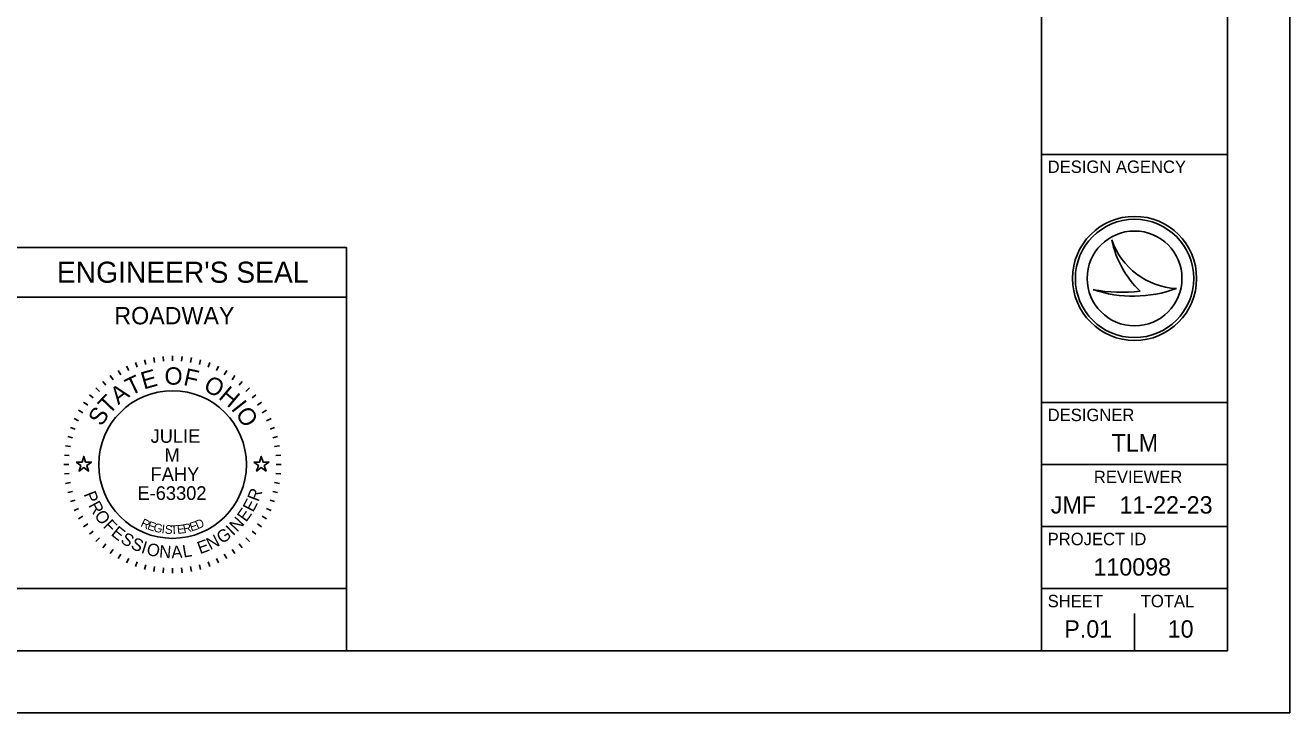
# Model space of a CAD drawing. Extents: x 0 to 34, y 0 to 22.
# Drawn here: x 23.81 to 34, y 0 to 5.54 of the extents above; entities that cross this region are included whole.
import ezdxf

# ---------------------------------------------------------------- set-up
doc = ezdxf.new("R2010")
doc.units = 0
for name, color, linetype in [('Default', 7, 'Continuous'), ('SH_Border', 7, 'Continuous'), ('SH_Cut_Line', 7, 'Continuous'), ('SH_Data', 7, 'Continuous')]:
    doc.layers.add(name, color=color, linetype=linetype)

msp = doc.modelspace()

# ---------------------------------------------------------------- linework, layer by layer
at = {"layer": 'Default'}
for points in [[(24.224, 2.02), (24.271, 2.02), (24.285, 2.065), (24.299, 2.02), (24.346, 2.02), (24.308, 1.992), (24.323, 1.948), (24.285, 1.975), (24.247, 1.948), (24.262, 1.992)], [(25.654, 2.02), (25.701, 2.02), (25.715, 2.065), (25.729, 2.02), (25.776, 2.02), (25.738, 1.992), (25.753, 1.948), (25.715, 1.975), (25.677, 1.948), (25.692, 1.992)]]:
    msp.add_lwpolyline(points, close=True, dxfattribs=at)
at = {"layer": 'SH_Border'}
for p, q in [((32, 0.5), (32, 21.5)), ((32, 4.5), (33.5, 4.5)), ((32, 2.5), (33.5, 2.5)), ((32, 2), (33.5, 2)), ((32, 1.5), (33.5, 1.5)), ((32, 1), (33.5, 1))]:
    msp.add_line(p, q, dxfattribs=at)
msp.add_lwpolyline([(1.5, 21.5), (33.5, 21.5), (33.5, 0.5), (1.5, 0.5)], close=True, dxfattribs=at)
at = {"layer": 'SH_Cut_Line'}
msp.add_lwpolyline([(0, 0), (34, 0), (34, 22), (0, 22)], close=True, dxfattribs=at)
at = {"layer": 'SH_Data'}
for p, q in [((32.567, 3.81), (32.567, 3.81)), ((23.6, 3.75), (26.4, 3.75)), ((26.4, 3.75), (26.4, 0.5)), ((32.75, 3.5), (32.75, 3.5)), ((32.417, 3.41), (32.417, 3.41)), ((33.087, 3.419), (33.087, 3.419)), ((23.6, 3.35), (26.4, 3.35)), ((24.848, 2.862), (24.855, 2.822)), ((24.924, 2.872), (24.927, 2.832)), ((25, 2.875), (25, 2.835)), ((25.076, 2.872), (25.073, 2.832)), ((25.152, 2.862), (25.145, 2.822)), ((24.563, 2.758), (24.583, 2.723)), ((24.63, 2.793), (24.647, 2.757)), ((24.701, 2.822), (24.714, 2.785)), ((24.774, 2.845), (24.784, 2.807)), ((25.226, 2.845), (25.216, 2.807)), ((25.299, 2.822), (25.286, 2.785)), ((25.37, 2.793), (25.353, 2.757)), ((25.437, 2.758), (25.417, 2.723)), ((24.438, 2.67), (24.463, 2.64)), ((24.498, 2.717), (24.521, 2.684)), ((25.502, 2.717), (25.479, 2.684)), ((25.562, 2.67), (25.537, 2.64)), ((24.33, 2.562), (24.36, 2.537)), ((24.381, 2.619), (24.41, 2.59)), ((25.619, 2.619), (25.59, 2.59)), ((25.67, 2.562), (25.64, 2.537)), ((24.283, 2.502), (24.316, 2.479)), ((25.717, 2.502), (25.684, 2.479)), ((24.207, 2.37), (24.243, 2.353)), ((24.242, 2.438), (24.277, 2.418)), ((25.758, 2.438), (25.723, 2.418)), ((25.793, 2.37), (25.757, 2.353)), ((24.178, 2.299), (24.215, 2.286)), ((25.822, 2.299), (25.785, 2.286)), ((24.138, 2.152), (24.178, 2.145)), ((24.155, 2.226), (24.193, 2.216)), ((25.845, 2.226), (25.807, 2.216)), ((25.862, 2.152), (25.822, 2.145)), ((24.128, 2.076), (24.168, 2.073)), ((25.872, 2.076), (25.832, 2.073)), ((24.125, 2), (24.165, 2)), ((25.875, 2), (25.835, 2)), ((24.128, 1.924), (24.168, 1.927)), ((24.138, 1.848), (24.178, 1.855)), ((25.862, 1.848), (25.822, 1.855)), ((25.872, 1.924), (25.832, 1.927)), ((24.155, 1.774), (24.193, 1.784)), ((25.845, 1.774), (25.807, 1.784)), ((24.178, 1.701), (24.215, 1.714)), ((24.207, 1.63), (24.243, 1.647)), ((25.793, 1.63), (25.757, 1.647)), ((25.822, 1.701), (25.785, 1.714)), ((24.242, 1.563), (24.277, 1.583)), ((25.758, 1.563), (25.723, 1.583)), ((24.283, 1.498), (24.316, 1.521)), ((24.33, 1.438), (24.36, 1.463)), ((25.67, 1.438), (25.64, 1.463)), ((25.717, 1.498), (25.684, 1.521)), ((24.381, 1.381), (24.41, 1.41)), ((24.438, 1.33), (24.463, 1.36)), ((25.562, 1.33), (25.537, 1.36)), ((25.619, 1.381), (25.59, 1.41)), ((24.498, 1.283), (24.521, 1.316)), ((24.563, 1.242), (24.583, 1.277)), ((24.63, 1.207), (24.647, 1.243)), ((25.37, 1.207), (25.353, 1.243)), ((25.437, 1.242), (25.417, 1.277)), ((25.502, 1.283), (25.479, 1.316)), ((24.701, 1.178), (24.714, 1.215)), ((24.774, 1.155), (24.784, 1.193)), ((24.848, 1.138), (24.855, 1.178)), ((24.924, 1.128), (24.927, 1.168)), ((25, 1.125), (25, 1.165)), ((25.076, 1.128), (25.073, 1.168)), ((25.152, 1.138), (25.145, 1.178)), ((25.226, 1.155), (25.216, 1.193)), ((25.299, 1.178), (25.286, 1.215)), ((32.75, 0.5), (32.75, 0.8)), ((32.375, 0.675), (32.375, 0.675)), ((23.6, 0.5), (26.4, 0.5)), ((23.6, 0.5), (26.4, 0.5))]:
    msp.add_line(p, q, dxfattribs=at)
msp.add_lwpolyline([(23.6, 0.5), (23.6, 1), (26.4, 1), (26.4, 0.5)], close=True, dxfattribs=at)
for centre, radius in [((32.75, 3.5), 0.5), ((32.75, 3.5), 0.477), ((32.75, 3.5), 0.477), ((32.75, 3.5), 0.382), ((25, 2), 0.595)]:
    msp.add_circle(centre, radius, dxfattribs=at)
for centre, radius, start, end in [((33.116, 3.998), 0.58, 198.9257, 198.9319), ((33.347, 3.97), 0.796, 191.6379, 191.6421), ((33.116, 3.998), 0.58, 198.9319, 267.1657), ((33.347, 3.97), 0.796, 191.6421, 226.0947), ((32.739, 4.37), 1.013, 251.4576, 290.0832), ((32.648, 4.654), 1.266, 259.4964, 259.4995), ((32.739, 4.37), 1.013, 251.4527, 251.4576), ((32.648, 4.654), 1.266, 259.4995, 276.6672)]:
    msp.add_arc(centre, radius, start, end, dxfattribs=at)

# ---------------------------------------------------------------- texts
for s, height, p in [('DESIGN AGENCY', 0.1, (32.05, 4.35)), ("ENGINEER'S SEAL", 0.17, (24.068, 3.465)), ('ROADWAY', 0.14, (24.531, 3.13)), ('DESIGNER', 0.1, (32.05, 2.35)), ('JULIE', 0.11, (24.823, 2.175)), ('TLM', 0.14, (32.565, 2.105)), ('M', 0.11, (24.935, 2.022)), ('FAHY', 0.11, (24.823, 1.868)), ('REVIEWER', 0.1, (32.422, 1.85)), ('E-63302', 0.11, (24.717, 1.715)), ('JMF', 0.14, (32.075, 1.605)), ('11-22-23', 0.14, (32.629, 1.605)), ('PROJECT ID', 0.1, (32.05, 1.35)), ('110098', 0.14, (32.419, 1.105)), ('SHEET', 0.1, (32.05, 0.85)), ('TOTAL', 0.1, (32.8, 0.85)), ('P.01', 0.14, (32.184, 0.605)), ('10', 0.14, (33.017, 0.605))]:
    msp.add_text(s, height=height, dxfattribs=at).set_placement(p)
for s, height, rotation, p in [('E', 0.14, 15.7571, (24.768, 2.604)), ('O', 0.14, 359.7812, (24.935, 2.644)), ('F', 0.14, 347.4362, (25.081, 2.642)), ('T', 0.14, 25.7167, (24.662, 2.552)), ('O', 0.14, 332.2586, (25.24, 2.602)), ('T', 0.14, 46.4344, (24.488, 2.396)), ('A', 0.14, 36.4747, (24.563, 2.478)), ('H', 0.14, 319.9136, (25.363, 2.536)), ('S', 0.14, 57.1924, (24.428, 2.301)), ('I', 0.14, 308.367, (25.466, 2.448)), ('O', 0.14, 303.1491, (25.502, 2.409)), ('P', 0.1, 291.494, (24.282, 1.762)), ('R', 0.1, 69.2322, (25.692, 1.695)), ('R', 0.1, 298.7311, (24.319, 1.672)), ('E', 0.1, 54.758, (25.593, 1.531)), ('E', 0.1, 61.9951, (25.648, 1.61)), ('O', 0.1, 306.4666, (24.365, 1.588)), ('F', 0.1, 314.7068, (24.434, 1.498)), ('R', 0.07, 334.487, (24.737, 1.505)), ('E', 0.07, 341.04, (24.791, 1.48)), ('E', 0.07, 17.6836, (25.15, 1.46)), ('D', 0.07, 23.3052, (25.201, 1.477)), ('N', 0.1, 47.0224, (25.52, 1.451)), ('E', 0.1, 321.4393, (24.498, 1.435)), ('S', 0.1, 328.6764, (24.574, 1.375)), ('G', 0.07, 347.4752, (24.841, 1.462)), ('I', 0.07, 353.7858, (24.909, 1.447)), ('S', 0.07, 356.8926, (24.936, 1.443)), ('T', 0.07, 3.0061, (24.986, 1.439)), ('E', 0.07, 6.0117, (25.039, 1.441)), ('R', 0.07, 11.9184, (25.092, 1.447)), ('N', 0.1, 27.3113, (25.304, 1.308)), ('G', 0.1, 35.0469, (25.398, 1.357)), ('I', 0.1, 43.287, (25.487, 1.421)), ('S', 0.1, 335.9134, (24.656, 1.327)), ('I', 0.1, 343.1505, (24.741, 1.29)), ('O', 0.1, 346.8859, (24.784, 1.275)), ('N', 0.1, 355.1261, (24.889, 1.252)), ('A', 0.1, 2.8617, (24.992, 1.244)), ('L', 0.1, 10.0987, (25.089, 1.249)), ('E', 0.1, 20.0742, (25.221, 1.277))]:
    msp.add_text(s, height=height, rotation=rotation, dxfattribs=at).set_placement(p)

doc.saveas('drawing.dxf')
